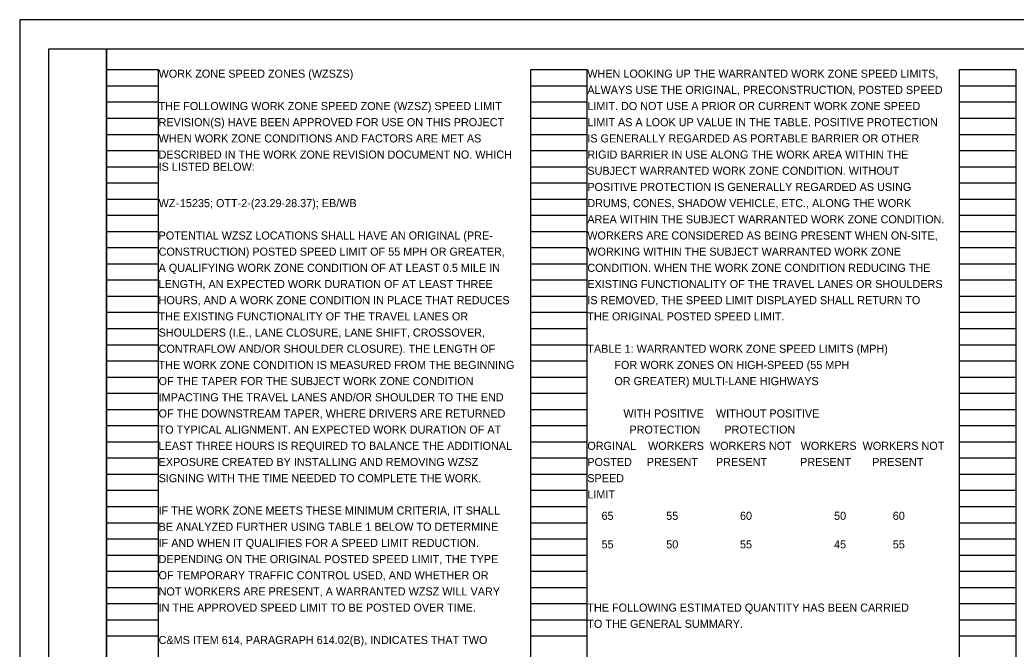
# Model space of a CAD drawing. Extents: x 0 to 34, y 0 to 22.
# Drawn here: x 0 to 17.24, y 11.11 to 22 of the extents above; entities that cross this region are included whole.
import ezdxf

# ---------------------------------------------------------------- set-up
doc = ezdxf.new("R2010")
doc.units = 0
for name, color, linetype in [('SH_Border', 7, 'Continuous'), ('SH_Cut_Line', 7, 'Continuous'), ('SH_Data', 7, 'Continuous'), ('SH_Text', 7, 'Continuous')]:
    doc.layers.add(name, color=color, linetype=linetype)

msp = doc.modelspace()

# ---------------------------------------------------------------- linework, layer by layer
at = {"layer": 'SH_Border'}
for points in [[(0.5, 21.5), (1.5, 21.5), (1.5, 0.5), (0.5, 0.5)], [(1.5, 21.5), (33.5, 21.5), (33.5, 0.5), (1.5, 0.5)]]:
    msp.add_lwpolyline(points, close=True, dxfattribs=at)
at = {"layer": 'SH_Cut_Line'}
msp.add_lwpolyline([(0, 0), (34, 0), (34, 22), (0, 22)], close=True, dxfattribs=at)
at = {"layer": 'SH_Data'}
for p, q in [((1.5, 0.98), (1.5, 21.14)), ((1.5, 21.14), (2.4, 21.14)), ((2.4, 0.98), (2.4, 21.14)), ((8.84, 0.98), (8.84, 21.14)), ((8.84, 21.14), (9.82, 21.14)), ((9.82, 0.98), (9.82, 21.14)), ((16.26, 0.98), (16.26, 21.14)), ((16.26, 21.14), (17.24, 21.14)), ((17.24, 0.98), (17.24, 21.14)), ((1.5, 20.86), (2.4, 20.86)), ((8.84, 20.86), (9.82, 20.86)), ((16.26, 20.86), (17.24, 20.86)), ((1.5, 20.58), (2.4, 20.58)), ((8.84, 20.58), (9.82, 20.58)), ((16.26, 20.58), (17.24, 20.58)), ((1.5, 20.3), (2.4, 20.3)), ((8.84, 20.3), (9.82, 20.3)), ((16.26, 20.3), (17.24, 20.3)), ((1.5, 20.02), (2.4, 20.02)), ((8.84, 20.02), (9.82, 20.02)), ((16.26, 20.02), (17.24, 20.02)), ((1.5, 19.74), (2.4, 19.74)), ((8.84, 19.74), (9.82, 19.74)), ((16.26, 19.74), (17.24, 19.74)), ((1.5, 19.46), (2.4, 19.46)), ((8.84, 19.46), (9.82, 19.46)), ((16.26, 19.46), (17.24, 19.46)), ((1.5, 19.18), (2.4, 19.18)), ((8.84, 19.18), (9.82, 19.18)), ((16.26, 19.18), (17.24, 19.18)), ((1.5, 18.9), (2.4, 18.9)), ((8.84, 18.9), (9.82, 18.9)), ((16.26, 18.9), (17.24, 18.9)), ((1.5, 18.62), (2.4, 18.62)), ((8.84, 18.62), (9.82, 18.62)), ((16.26, 18.62), (17.24, 18.62)), ((1.5, 18.34), (2.4, 18.34)), ((8.84, 18.34), (9.82, 18.34)), ((16.26, 18.34), (17.24, 18.34)), ((1.5, 18.06), (2.4, 18.06)), ((8.84, 18.06), (9.82, 18.06)), ((16.26, 18.06), (17.24, 18.06)), ((1.5, 17.78), (2.4, 17.78)), ((8.84, 17.78), (9.82, 17.78)), ((16.26, 17.78), (17.24, 17.78)), ((1.5, 17.5), (2.4, 17.5)), ((8.84, 17.5), (9.82, 17.5)), ((16.26, 17.5), (17.24, 17.5)), ((1.5, 17.22), (2.4, 17.22)), ((8.84, 17.22), (9.82, 17.22)), ((16.26, 17.22), (17.24, 17.22)), ((1.5, 16.94), (2.4, 16.94)), ((8.84, 16.94), (9.82, 16.94)), ((16.26, 16.94), (17.24, 16.94)), ((1.5, 16.66), (2.4, 16.66)), ((8.84, 16.66), (9.82, 16.66)), ((16.26, 16.66), (17.24, 16.66)), ((1.5, 16.38), (2.4, 16.38)), ((8.84, 16.38), (9.82, 16.38)), ((16.26, 16.38), (17.24, 16.38)), ((1.5, 16.1), (2.4, 16.1)), ((8.84, 16.1), (9.82, 16.1)), ((16.26, 16.1), (17.24, 16.1)), ((1.5, 15.82), (2.4, 15.82)), ((8.84, 15.82), (9.82, 15.82)), ((16.26, 15.82), (17.24, 15.82)), ((1.5, 15.54), (2.4, 15.54)), ((8.84, 15.54), (9.82, 15.54)), ((16.26, 15.54), (17.24, 15.54)), ((1.5, 15.26), (2.4, 15.26)), ((8.84, 15.26), (9.82, 15.26)), ((16.26, 15.26), (17.24, 15.26)), ((1.5, 14.98), (2.4, 14.98)), ((8.84, 14.98), (9.82, 14.98)), ((16.26, 14.98), (17.24, 14.98)), ((1.5, 14.7), (2.4, 14.7)), ((8.84, 14.7), (9.82, 14.7)), ((16.26, 14.7), (17.24, 14.7)), ((1.5, 14.42), (2.4, 14.42)), ((8.84, 14.42), (9.82, 14.42)), ((16.26, 14.42), (17.24, 14.42)), ((1.5, 14.14), (2.4, 14.14)), ((8.84, 14.14), (9.82, 14.14)), ((16.26, 14.14), (17.24, 14.14)), ((1.5, 13.86), (2.4, 13.86)), ((8.84, 13.86), (9.82, 13.86)), ((16.26, 13.86), (17.24, 13.86)), ((1.5, 13.58), (2.4, 13.58)), ((8.84, 13.58), (9.82, 13.58)), ((16.26, 13.58), (17.24, 13.58)), ((1.5, 13.3), (2.4, 13.3)), ((8.84, 13.3), (9.82, 13.3)), ((16.26, 13.3), (17.24, 13.3)), ((1.5, 13.02), (2.4, 13.02)), ((8.84, 13.02), (9.82, 13.02)), ((16.26, 13.02), (17.24, 13.02)), ((1.5, 12.74), (2.4, 12.74)), ((8.84, 12.74), (9.82, 12.74)), ((16.26, 12.74), (17.24, 12.74)), ((1.5, 12.46), (2.4, 12.46)), ((8.84, 12.46), (9.82, 12.46)), ((16.26, 12.46), (17.24, 12.46)), ((1.5, 12.18), (2.4, 12.18)), ((8.84, 12.18), (9.82, 12.18)), ((16.26, 12.18), (17.24, 12.18)), ((1.5, 11.9), (2.4, 11.9)), ((8.84, 11.9), (9.82, 11.9)), ((16.26, 11.9), (17.24, 11.9)), ((1.5, 11.62), (2.4, 11.62)), ((8.84, 11.62), (9.82, 11.62)), ((16.26, 11.62), (17.24, 11.62)), ((1.5, 11.34), (2.4, 11.34)), ((8.84, 11.34), (9.82, 11.34)), ((16.26, 11.34), (17.24, 11.34))]:
    msp.add_line(p, q, dxfattribs=at)

# ---------------------------------------------------------------- texts
at = {"layer": 'SH_Text'}
for s, p in [('WORK ZONE SPEED ZONES (WZSZS)', (2.4, 21)), ('WHEN LOOKING UP THE WARRANTED WORK ZONE SPEED LIMITS,', (9.82, 21)), ('ALWAYS USE THE ORIGINAL, PRECONSTRUCTION, POSTED SPEED', (9.82, 20.72)), ('THE FOLLOWING WORK ZONE SPEED ZONE (WZSZ) SPEED LIMIT', (2.4, 20.44)), ('LIMIT. DO NOT USE A PRIOR OR CURRENT WORK ZONE SPEED', (9.82, 20.44)), ('REVISION(S) HAVE BEEN APPROVED FOR USE ON THIS PROJECT', (2.4, 20.16)), ('LIMIT AS A LOOK UP VALUE IN THE TABLE. POSITIVE PROTECTION', (9.82, 20.16)), ('WHEN WORK ZONE CONDITIONS AND FACTORS ARE MET AS', (2.4, 19.88)), ('IS GENERALLY REGARDED AS PORTABLE BARRIER OR OTHER', (9.82, 19.88)), ('DESCRIBED IN THE WORK ZONE REVISION DOCUMENT NO. WHICH', (2.4, 19.6)), ('RIGID BARRIER IN USE ALONG THE WORK AREA WITHIN THE', (9.82, 19.6)), ('IS LISTED BELOW:', (2.4, 19.39)), ('SUBJECT WARRANTED WORK ZONE CONDITION. WITHOUT', (9.82, 19.32)), ('POSITIVE PROTECTION IS GENERALLY REGARDED AS USING', (9.82, 19.04)), ('WZ-', (2.4, 18.76)), ('15235; OTT-2-(23.29-28.37); EB/WB', (2.769, 18.76)), ('DRUMS, CONES, SHADOW VEHICLE, ETC., ALONG THE WORK', (9.82, 18.76)), ('AREA WITHIN THE SUBJECT WARRANTED WORK ZONE CONDITION.', (9.82, 18.48)), ('POTENTIAL WZSZ LOCATIONS SHALL HAVE AN ORIGINAL (PRE-', (2.4, 18.2)), ('WORKERS ARE CONSIDERED AS BEING PRESENT WHEN ON-SITE,', (9.82, 18.2)), ('CONSTRUCTION) POSTED SPEED LIMIT OF 55 MPH OR GREATER,', (2.4, 17.92)), ('WORKING WITHIN THE SUBJECT WARRANTED WORK ZONE', (9.82, 17.92)), ('A QUALIFYING WORK ZONE CONDITION OF AT LEAST 0.5 MILE IN', (2.4, 17.64)), ('CONDITION. WHEN THE WORK ZONE CONDITION REDUCING THE', (9.82, 17.64)), ('LENGTH, AN EXPECTED WORK DURATION OF AT LEAST THREE', (2.4, 17.36)), ('EXISTING FUNCTIONALITY OF THE TRAVEL LANES OR SHOULDERS', (9.82, 17.36)), ('HOURS, AND A WORK ZONE CONDITION IN PLACE THAT REDUCES', (2.4, 17.08)), ('IS REMOVED, THE SPEED LIMIT DISPLAYED SHALL RETURN TO', (9.82, 17.08)), ('THE EXISTING FUNCTIONALITY OF THE TRAVEL LANES OR', (2.4, 16.8)), ('THE ORIGINAL POSTED SPEED LIMIT.', (9.82, 16.8)), ('SHOULDERS (I.E., LANE CLOSURE, LANE SHIFT, CROSSOVER,', (2.4, 16.52)), ('CONTRAFLOW AND/OR SHOULDER CLOSURE). THE LENGTH OF', (2.4, 16.24)), ('TABLE 1: WARRANTED WORK ZONE SPEED LIMITS (MPH)', (9.82, 16.24)), ('THE WORK ZONE CONDITION IS MEASURED FROM THE BEGINNING', (2.4, 15.96)), ('         FOR WORK ZONES ON HIGH-SPEED (55 MPH', (9.82, 15.96)), ('OF THE TAPER FOR THE SUBJECT WORK ZONE CONDITION', (2.4, 15.68)), ('         OR GREATER) MULTI-LANE HIGHWAYS', (9.82, 15.68)), ('IMPACTING THE TRAVEL LANES AND/OR SHOULDER TO THE END', (2.4, 15.4)), ('OF THE DOWNSTREAM TAPER, WHERE DRIVERS ARE RETURNED', (2.4, 15.12)), ('            WITH POSITIVE    WITHOUT POSITIVE', (9.82, 15.12)), ('TO TYPICAL ALIGNMENT. AN EXPECTED WORK DURATION OF AT', (2.4, 14.84)), ('              PROTECTION        PROTECTION', (9.82, 14.84)), ('LEAST THREE HOURS IS REQUIRED TO BALANCE THE ADDITIONAL', (2.4, 14.56)), ('ORGINAL    WORKERS  WORKERS NOT   WORKERS  WORKERS NOT', (9.82, 14.56)), ('EXPOSURE CREATED BY INSTALLING AND REMOVING WZSZ', (2.4, 14.28)), ('POSTED     PRESENT      PRESENT           PRESENT       PRESENT', (9.82, 14.28)), ('SIGNING WITH THE TIME NEEDED TO COMPLETE THE WORK.', (2.4, 14)), ('SPEED', (9.82, 14)), ('LIMIT', (9.82, 13.72)), ('IF THE WORK ZONE MEETS THESE MINIMUM CRITERIA, IT SHALL', (2.4, 13.44)), (' 65        ', (10.014, 13.349)), (' 55      ', (11.134, 13.349)), ('    60              ', (12.254, 13.349)), ('   50 ', (13.934, 13.349)), (' 60', (15.054, 13.349)), ('BE ANALYZED FURTHER USING TABLE 1 BELOW TO DETERMINE', (2.4, 13.16)), ('IF AND WHEN IT QUALIFIES FOR A SPEED LIMIT REDUCTION.', (2.4, 12.88)), (' 55        ', (10.014, 12.855)), (' 50      ', (11.134, 12.855)), ('    55              ', (12.254, 12.855)), ('   45 ', (13.934, 12.855)), (' 55', (15.054, 12.855)), ('DEPENDING ON THE ORIGINAL POSTED SPEED LIMIT, THE TYPE', (2.4, 12.6)), ('OF TEMPORARY TRAFFIC CONTROL USED, AND WHETHER OR', (2.4, 12.32)), ('NOT WORKERS ARE PRESENT, A WARRANTED WZSZ WILL VARY', (2.4, 12.04)), ('IN THE APPROVED SPEED LIMIT TO BE POSTED OVER TIME.', (2.4, 11.76)), ('THE FOLLOWING ESTIMATED QUANTITY HAS BEEN CARRIED', (9.82, 11.76)), ('TO THE GENERAL SUMMARY.', (9.82, 11.48)), ('C&MS ITEM 614, PARAGRAPH 614.02(B), INDICATES THAT TWO', (2.4, 11.2))]:
    msp.add_text(s, height=0.14, dxfattribs=at).set_placement(p)

doc.saveas('drawing.dxf')
